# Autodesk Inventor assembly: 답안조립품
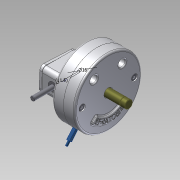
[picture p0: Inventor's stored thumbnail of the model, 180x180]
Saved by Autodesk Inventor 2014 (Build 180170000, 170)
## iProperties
Created: 2015-04
Part Number: 답안조립품
Document SubType Name: Assembly
Designer: Administrator
Author: Administrator
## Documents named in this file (15)
- C:\Documents and Settings\Administrator\바탕 화면\350406V1029\답안조립품.iam
- C:\Documents and Settings\Administrator\바탕 화면\350406V1029\본체.ipt
- C:\Documents and Settings\Administrator\바탕 화면\350406V1029\가변스프링.ipt
- C:\Documents and Settings\Administrator\바탕 화면\350406V1029\커버.ipt
- C:\Documents and Settings\Administrator\바탕 화면\350406V1029\M 10 x 35.ipt
- C:\Documents and Settings\Administrator\바탕 화면\350406V1029\베어링62_22.ipt
- C:\Documents and Settings\Administrator\바탕 화면\350406V1029\커버2.ipt
- C:\Documents and Settings\Administrator\바탕 화면\350406V1029\M 5 x 12.ipt
- C:\Documents and Settings\Administrator\바탕 화면\350406V1029\축.ipt
- C:\Documents and Settings\Administrator\바탕 화면\350406V1029\멈춤링.ipt
- C:\Documents and Settings\Administrator\바탕 화면\350406V1029\슬라이더3.ipt
- C:\Documents and Settings\Administrator\바탕 화면\350406V1029\부시.ipt
- C:\Documents and Settings\Administrator\바탕 화면\350406V1029\슬라이더2.ipt
- C:\Documents and Settings\Administrator\바탕 화면\350406V1029\슬라이더.ipt
- C:\Documents and Settings\Administrator\바탕 화면\350406V1029\평행핀.ipt
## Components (6 placed, 4 different names)
1. 가변스프링:1
2. M 10 x 35:1
3. M 10 x 35:2
4. M 5 x 12:1
5. M 5 x 12:2
6. KS B 1320 B B 5 x  20:1 — 플러쉬:1
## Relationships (1: Flush 1)
- 플러쉬:1 [Flush]: KS B 1320 B B 5 x  20:1
